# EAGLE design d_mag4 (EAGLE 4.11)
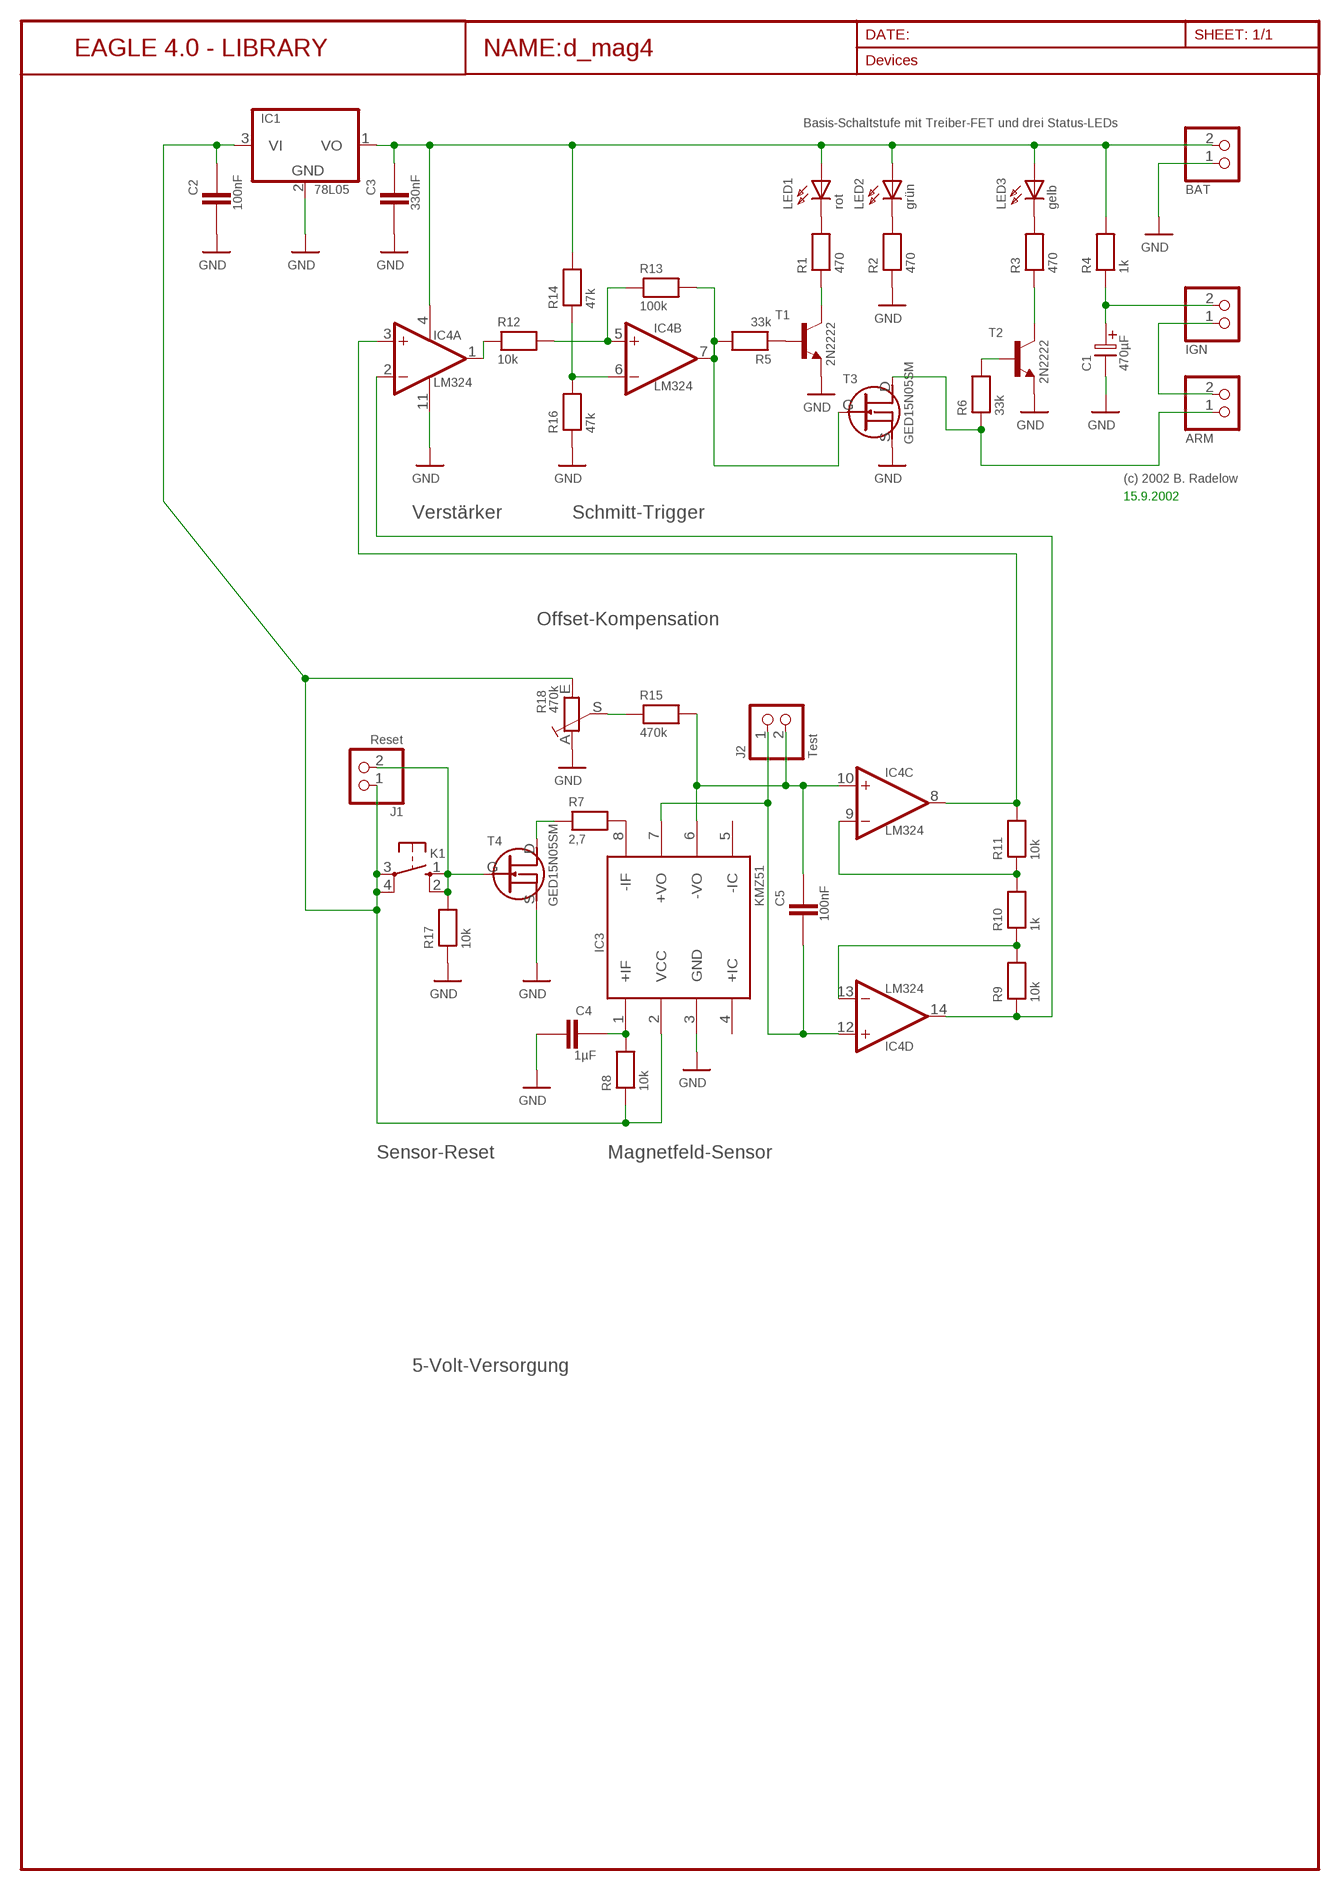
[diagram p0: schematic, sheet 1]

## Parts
ARM  PFOSTEN_1X2  [1X02]
BAT  PFOSTEN_1X2  [1X02]
C1  470µF  EC_470U  [E5-10,5]
C2  100nF  MKS2_10N-150N  [C5B2.5]
C3  330nF  MKS2_330N  [C5B3.5]
C4  1µF  MKS2_1000N  [C5B5]
C5  100nF  MKS2_10N-150N  [C5B2.5]
IC1  78L05  [TO92]
IC3  KMZ51  [SO8]
IC4  LM324  [DIL14]
IGN  PFOSTEN_1X2  [1X02]
J1  Reset  PFOSTEN_1X2  [1X02]
J2  Test  PFOSTEN_1X2  [1X02]
K1  TASTER_OMRON  [B3F-10XX]
LED1  rot  LED_3MM  [LED3MM]
LED2  grün  LED_3MM  [LED3MM]
LED3  gelb  LED_3MM  [LED3MM]
R1  470  R7,5  [0207/7]
R2  470  R7,5  [0207/7]
R3  470  R7,5  [0207/7]
R4  1k  R7,5  [0207/7]
R5  33k  R7,5  [0207/7]
R6  33k  R7,5  [0207/7]
R7  2,7  R7,5  [0207/7]
R8  10k  R7,5  [0207/7]
R9  10k  R7,5  [0207/7]
R10  1k  R7,5  [0207/7]
R11  10k  R7,5  [0207/7]
R12  10k  R7,5  [0207/7]
R13  100k  R7,5  [0207/7]
R14  47k  R7,5  [0207/7]
R15  470k  R7,5  [0207/7]
R16  47k  R7,5  [0207/7]
R17  10k  R7,5  [0207/7]
R18  470k  TRIM-S64Y  [S64Y]
T1  2N2222  [TO18]
T2  2N2222  [TO18]
T3  GED15N05SM  [TO252]
T4  GED15N05SM  [TO252]

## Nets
5VOLT: C2.1 IC1.3(VI) IC3.2(VCC) J1.1 K1.3(P) K1.4(P1) R8.1 R18.E(1E)
GND: BAT.1 C1.- C2.2 C3.2 C4.2 IC1.2(GND) IC3.3(GND) IC4.11(A:GND) R2.1 R16.1 R17.1 R18.A(1A) T1.1(E) T2.1(E) T3.S T4.S
N$1: ARM.2 IGN.1
N$2: LED2.K(C) R2.2
N$3: LED1.K(C) R1.2
N$4: LED3.K(C) R3.2
N$6: IC4.7(B:OUT) R5.2 R13.2 T3.G
N$8: ARM.1 R6.1 T3.D
N$11: C1.+ IGN.2 R4.1
N$12: R5.1 T1.2(B)
N$16: IC4.5(B:+IN) R12.2 R13.1
N$17: R1.1 T1.3(C)
N$18: IC4.6(B:-IN) R14.1 R16.2
N$19: IC4.9(C:-IN) R10.2 R11.1
N$20: IC4.13(D:-IN) R9.2 R10.1
N$21: IC4.2(A:-IN) IC4.14(D:OUT) R9.1
N$22: IC4.3(A:+IN) IC4.8(C:OUT) R11.2
N$23: C4.1 IC3.1(+IF) R8.2
N$24: C5.2 IC3.7(+VO) IC4.12(D:+IN) J2.1
N$25: R3.1 T2.3(C)
N$26: J1.2 K1.1(S) K1.2(S1) R17.2 T4.G
N$27: R6.2 T2.2(B)
N$28: C5.1 IC3.6(-VO) IC4.10(C:+IN) J2.2 R15.2
N$29: R15.1 R18.S(1S)
N$30: IC3.8(-IF) R7.2
N$31: IC4.1(A:OUT) R12.1
N$37: R7.1 T4.D
V+: BAT.2 C3.1 IC1.1(VO) IC4.4(A:V+) LED1.A LED2.A LED3.A R4.2 R14.2
Unconnected: IC3.4(+IC) IC3.5(-IC)

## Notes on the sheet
- Basis-Schaltstufe mit Treiber-FET und drei Status-LEDs
- (c) 2002 B. Radelow
- 15.9.2002
- Verstärker | Schmitt-Trigger
- Offset-Kompensation
- Sensor-Reset | Magnetfeld-Sensor
- 5-Volt-Versorgung

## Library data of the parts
ARM BAT IGN J1 J2 = _d_serie:PFOSTEN_1X2: Pfosten 2x1
C1 = _d_serie:EC_470U: 470µF 16V, Höhe 17mm
C2 C5 = _d_serie:MKS2_10N-150N: WIMA MKS2 Folienkondensator
C3 = _d_serie:MKS2_330N: WIMA MKS2 Folienkondensator 330nF
C4 = _d_serie:MKS2_1000N: WIMA MKS2 Folienkondensator 1µF
IC1 = _d_serie:78L05: Voltage Regulator 5V
IC3 = _d_serie:KMZ51: Magnetic Field Sensor
IC4 = _d_serie:LM324: LM324 - quad OpAmp
K1 = _d_serie:TASTER_OMRON: Taster, Omron
LED1-LED3 = _d_serie:LED_3MM
R1-R17 = _d_serie:R7,5: Widerstand 0,3 Watt liegend
R18 = _d_serie:TRIM-S64Y: Trimmer S64Y
T1 T2 = _d_serie:2N2222
T3 T4 = _d_serie:GED15N05SM: N-Channel Power-FET

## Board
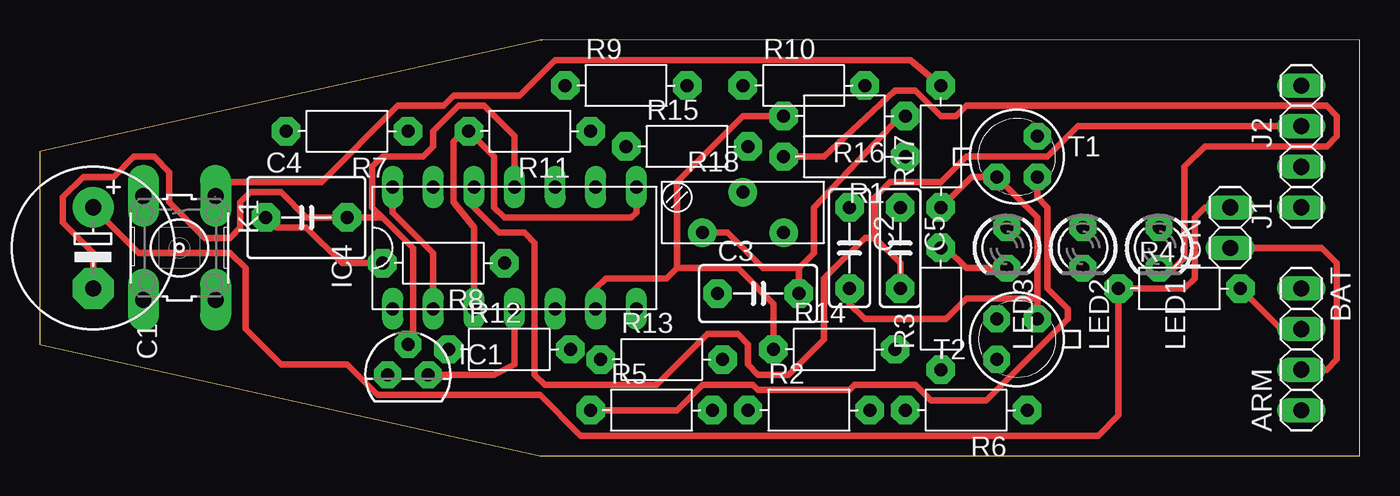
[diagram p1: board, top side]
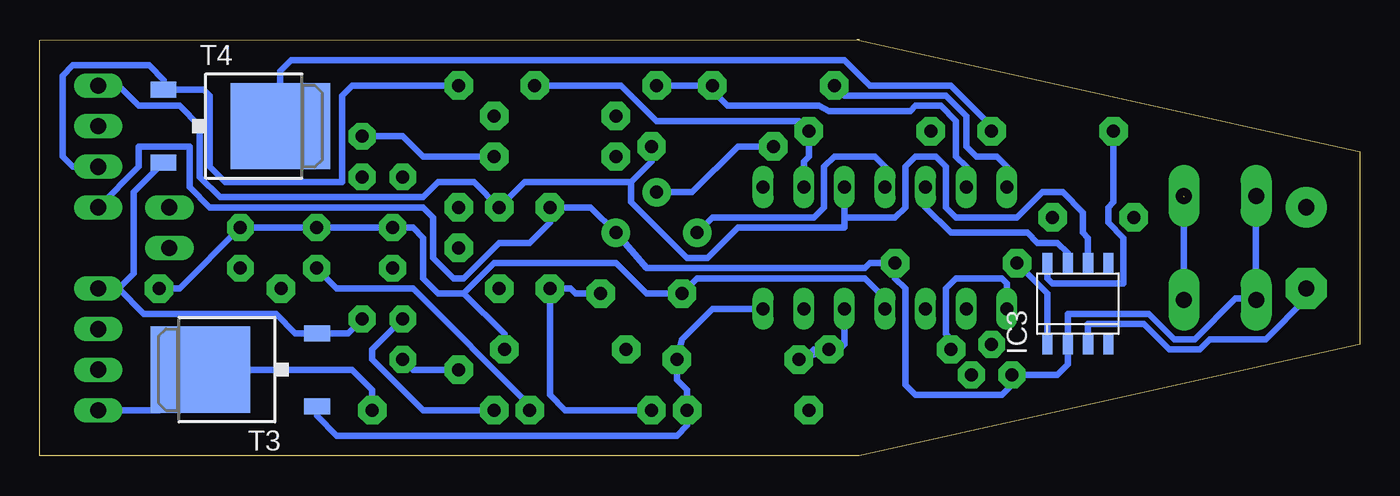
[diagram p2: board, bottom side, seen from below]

Size 82.54 x 26.04 mm. Coordinates in mm from the lower left corner, seen from the top.
Outline: 31.44,26.04 82.54,26.03 82.54,0 31.27,0 0,6.99 0,19.04 31.44,26.04
Outline: 31.27,26.04 31.44,26.04
Copper layers (1*16): Top 0.035mm / dielectric 1.5mm / Bottom 0.035mm
Design rules "default": minimum track width 10mil, minimum drill 24mil, track to track 8mil, track to pad 8mil, pad to pad 8mil, via to via 8mil, smd to smd 8mil, copper to edge 40mil, drill to drill 8mil, minimum pad ring 10mil, minimum via ring 8mil, stop-mask expansion 4mil, vias tented up to drill 0mil, thermal gap 10mil

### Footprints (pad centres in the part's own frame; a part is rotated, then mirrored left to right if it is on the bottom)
1X02 = drill 1.016 long: 1 -1.27,0; 2 1.27,0
E5-10,5 = drill 1.016 pad 2.54 round: + -2.54,0 | drill 1.016 pad 2.54 octagon: - 2.54,0
C5B2.5 = drill 0.813 pad 1.778 octagon: 1 -2.54,0; 2 2.54,0
C5B3.5 = drill 0.813 pad 1.778 octagon: 1 -2.54,0; 2 2.54,0
C5B5 = drill 0.813 pad 1.778 octagon: 1 -2.54,0; 2 2.54,0
TO92 = drill 0.813 pad 1.676 octagon: 1 1.27,0; 2 0,1.905; 3 -1.27,0
SO8 = smd 0.635 x 1.27: 1 -1.905,-2.54; 2 -0.635,-2.54; 3 0.635,-2.54; 4 1.905,-2.54; 5 1.905,2.54; 6 0.635,2.54; 7 -0.635,2.54; 8 -1.905,2.54
DIL14 = drill 0.813 long: 1 -7.62,-3.81; 2 -5.08,-3.81; 3 -2.54,-3.81; 4 0,-3.81; 5 2.54,-3.81; 6 5.08,-3.81; 7 7.62,-3.81; 8 7.62,3.81; 9 5.08,3.81; 10 2.54,3.81; 11 0,3.81; 12 -2.54,3.81; 13 -5.08,3.81; 14 -7.62,3.81
B3F-10XX = drill 1.016 pad 1.93 long: 1 -3.251,2.261; 2 3.251,2.261; 3 -3.251,-2.261; 4 3.251,-2.261
LED3MM = drill 0.813 pad 1.676 octagon: A -1.27,0; K 1.27,0
0207/7 = drill 0.813 pad 1.778 octagon: 1 -3.81,0; 2 3.81,0
S64Y = drill 0.813 pad 1.778 round: A -2.54,-1.27; E 2.54,-1.27; S 0,1.27
TO18 = drill 0.813 pad 1.676 octagon: 1 -1.27,-1.27; 2 1.27,-1.27; 3 1.27,1.27
TO252 = smd 5.4 x 6.2: D 0,1.23 | smd 1 x 1.6: G -2.28,-6.07; S 2.28,-6.07

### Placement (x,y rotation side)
ARM  78.89,4.13 90 top
BAT  78.89,9.21 270 top
C1  3.33,13.02 270 top
C2  50.64,13.02 270 top
C3  44.92,10.16 0 top
C4  16.66,14.92 0 top
C5  53.81,13.02 270 top
IC1  23.01,5.08 0 top
IC3  17.61,9.53 0 bottom
IC4  29.68,13.02 0 top
IGN  74.45,14.29 90 top
J1  78.89,16.83 90 top
J2  78.89,21.91 90 top
K1  8.72,13.02 270 top
LED1  70,13.02 270 top
LED2  65.24,13.02 270 top
LED3  60.48,13.02 270 top
R1  50.32,18.73 180 top
R2  48.09,2.86 0 top
R3  56.35,9.21 90 top
R4  71.27,10.48 0 top
R5  38.25,2.86 0 top
R6  57.94,2.86 180 top
R7  19.2,20.32 180 top
R8  25.23,12.06 180 top
R9  36.66,23.18 0 top
R10  47.78,23.18 0 top
R11  30.63,20.32 180 top
R12  29.36,6.67 0 top
R13  38.89,6.03 0 top
R14  49.68,6.67 0 top
R15  40.47,19.37 0 top
R16  50.32,21.27 180 top
R17  56.35,19.37 90 top
R18  43.97,15.24 0 top
T1  61.11,18.73 0 top
T2  61.11,7.3 180 top
T3  71.27,5.4 90 bottom
T4  68.73,20.64 270 bottom

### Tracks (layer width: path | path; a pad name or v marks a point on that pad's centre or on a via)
5VOLT
  Top 0.406: IC1.3 21.11,4.76
  Bottom 0.406: J1.1 76.35,18.1 76.35,19.37 73.18,19.37 73.18,16.83 71.91,15.56 58.57,15.56 57.94,14.92 57.94,12.38 56.67,11.11 56.03,11.11 53.81,13.34 51.9,13.34 50.64,14.61 C2.1 48.09,15.56 R18.E 44.6,11.75 30.95,11.75 30.63,12.06 R8.1 29.04,11.11 28.41,10.48 28.41,4.44 27.78,3.81 22.38,3.81 21.74,4.44 IC1.3 | 6.46,10.83 6.5,10.79 | 6.46,10.83 6.46,11.07 6.5,10.79 | K1.4 6.46,10.83 | K1.3 6.5,17.5 6.5,10.79 | 18.25,5.72 IC3.2 | 21.43,5.08 21.43,5.4 IC1.3 | 21.43,5.08 IC1.3 | 21.43,5.08 19.52,5.08 18.89,5.08 18.25,5.72 | 18.25,5.72 18.25,8.89 13.17,8.89 11.58,7.3 10.31,7.3 7.77,9.84 6.5,9.84 6.5,10.79
GND
  Top 0.406: 47.46,11.75 45.24,11.75 43.01,13.97 R18.A | 21.43,14.92 20.79,15.56 20.79,18.1 21.43,18.73 23.97,18.73 24.6,19.37 24.6,20.32 26.19,21.91 27.78,21.91 29.68,20 IC4.11 | R17.1 58.25,17.46 T1.1 62.38,14.92 62.38,9.84 | 62.38,9.84 T2.1 | C2.2 50.64,9.53 51.59,8.57 56.67,8.57 57.94,9.84 62.38,9.84 | R16.1 53.81,21.27 48.41,15.56 48.41,12.7 47.46,11.75 | 47.46,11.75 C3.2 | IC1.2 23.33,7.3 23.33,13.02 21.43,14.92 | 21.43,14.92 C4.2 16.66,14.92 15.08,16.51 13.17,16.51 12.54,15.87 12.54,14.29 11.9,13.65 10.31,13.65 8.09,15.87 8.09,17.78 7.14,18.73 5.87,18.73 4.6,17.46 2.69,17.46 1.42,16.19 1.42,14.61 3.33,12.7 C1.-
  Bottom 0.406: T2.1 63.28,7.68 T3.S 66.57,7.68 67.78,8.89 76.03,8.89 77.62,10.48 | 77.62,10.48 BAT.1 | 77.62,10.48 76.67,11.43 76.67,16.51 74.82,18.36 T4.S | R2.1 49.68,2.86 50.64,3.81 C2.2 49.37,10.48 49.05,10.16 C3.2 | R18.A 40.47,14.92 34.12,14.92 33.49,15.56 33.49,18.1 32.86,18.73 30.32,18.73 29.68,18.1 IC4.11 | C1.- 3.33,9.84 5.87,7.3 9.36,7.3 9.99,6.67 11.9,6.67 13.49,8.26 16.98,8.26 IC3.3
N$1
  Top 0.406: ARM.2 80.48,5.4 81.12,6.03 81.12,12.06 80.16,13.02 IGN.1
N$2
  Bottom 0.406: R2.2 51.9,3.17 59.21,10.48 63.97,10.48 LED2.K
N$3
  Top 0.406: LED1.K 70.95,11.75 71.59,12.38 71.59,18.1 72.86,19.37 80.48,19.37 81.12,20 81.12,21.27 80.48,21.91 57.94,21.91 57.3,21.27 56.35,21.27 54.76,22.86 53.49,22.86 49.05,18.73 R1.2
N$4
  Top 0.406: R3.2 56.67,13.02 57.94,11.75 LED3.K
N$6
  Bottom 0.406: T3.G 65.2,2.5 63.97,1.27 42.7,1.27 42.06,1.91 R5.2 42.06,4.13 42.7,4.76 R13.2 42.38,7.3 40.47,9.21 IC4.7
N$8
  Bottom 0.406: ARM.1 75.08,2.86 72.54,5.4 | R6.1 61.75,4.13 63.02,5.4 72.54,5.4 | 72.54,5.4 T3.D
N$11
  Top 0.406: C1.+ 6.18,12.7 11.9,12.7 12.85,11.75 12.85,7.94 15.08,5.72 19.2,5.72 21.11,3.81 31.27,3.81 33.81,1.27 66.19,1.27 67.46,2.54 67.46,9.84 68.1,10.48 R4.1 71.59,10.48 72.23,11.11 72.23,14.92 72.86,15.56 IGN.2
N$12
  Top 0.406: R5.1 39.84,2.86 41.43,4.44 44.6,4.44 44.92,4.13 50.64,4.13 50.95,4.44 54.76,4.44 55.72,3.49 59.21,3.49 64.29,8.57 64.29,9.21 63.02,10.48 63.02,15.56 62.38,16.19 T1.2
N$16
  Bottom 0.406: R12.2 R13.1 34.76,6.03 34.12,6.67 R12.2 | R12.2 32.54,6.67 32.22,6.98 IC4.5
N$17
  Bottom 0.406: T1.3 59.84,20 58.57,18.73 R1.1
N$18
  Top 0.406: R14.1 45.87,9.53 43.65,11.75 39.84,11.75 | IC4.6 34.76,10.48 35.4,11.11 39.21,11.11 39.84,11.75 | R16.2 43.97,21.27 39.84,17.14 39.84,11.75
N$19
  Bottom 0.406: IC4.9 34.76,18.42 34.44,18.73 R11.1 35.08,20.95 43.97,20.95 46.19,23.18 R10.2
N$20
  Bottom 0.406: R10.1 R9.2 40.79,23.18 39.52,21.91 33.81,21.91 33.17,21.59 28.09,21.59 27.78,21.91 26.19,21.91 25.23,20.95 25.23,18.73 24.6,18.1 IC4.13
N$21
  Top 0.406: IC4.14 22.06,15.24 24.6,12.7 IC4.2
  Bottom 0.406: IC4.14 22.06,18.1 22.69,18.73 23.97,18.73 24.6,19.37 24.6,21.27 25.87,22.54 32.22,22.54 R9.1
N$22
  Top 0.406: IC4.3 27.14,14.29 25.87,15.87 25.87,19.69 26.51,20.32 R11.2 28.41,18.73 28.41,15.56 29.04,14.92 36.98,14.92 37.3,15.24 IC4.8
N$23
  Top 0.406: C4.1 14.76,14.29 16.66,14.29 18.89,12.06 R8.2
  Bottom 0.406: IC3.1 19.52,10.16 R8.2
N$24
  Top 0.406: 52.22,13.65 51.59,13.65 49.05,11.11 49.05,7.3 46.83,5.08 44.92,5.08 44.29,5.72 44.29,6.98 43.65,7.62 41.75,7.62 38.57,4.44 31.58,4.44 30.95,5.08 30.95,13.34 30.32,13.97 28.73,13.97 27.14,15.56 IC4.12 | J2.1 64.92,20.64 63.02,18.73 57.94,18.73 56.35,17.14 53.17,17.14 52.22,16.19 52.22,13.65 | 52.22,13.65 53.81,12.06 C5.2
  Bottom 0.406: IC3.7 18.25,12.7 18.89,13.34 20.15,13.34 20.79,13.97 25.55,13.97 27.14,15.56 IC4.12
N$25
  Bottom 0.406: T2.3 59.21,5.4 R3.1
N$26  (1 unrouted)
  Top 0.406: R17.2 54.45,24.76 32.22,24.76 30,22.54 25.87,22.54 25.23,21.91 22.38,21.91 17.61,17.14 11.9,17.14 10.95,16.19
  Bottom 0.406: K1.1 11.02,16.27 10.95,17.14 10.99,17.11 K1.1 | K1.2 K1.1 | J1.2 80.48,18.1 81.12,18.73 81.12,23.81 80.48,24.45 75.72,24.45 74.8,23.53 T4.G 72.28,22.92 71.91,22.54 71.91,18.1 70.95,17.14 63.65,17.14 63.65,22.54 63.02,23.18 R17.2
N$27
  Bottom 0.406: R6.2 58.57,2.86 61.75,6.03 61.75,6.67 T2.2
N$28
  Bottom 0.406: 32.22,14.92 32.22,14.29 38.89,14.29 40.79,12.38 42.06,12.38 45.55,15.87 45.55,17.14 | 32.22,14.92 IC4.10 | 45.55,17.14 44.29,18.42 R15.2 | 45.55,17.14 52.22,17.14 C5.1 55.4,17.14 57.62,17.14 58.57,16.19 71.27,16.19 72.54,17.46 72.54,20.64 73.81,21.91 76.35,21.91 77.62,23.18 J2.2 | IC3.6 16.98,13.65 17.3,13.97 17.3,15.24 18.57,16.51 19.84,16.51 21.43,14.92 25.23,14.92 25.87,15.56 25.87,18.1 26.51,18.73 27.78,18.73 28.41,18.1 28.41,15.56 29.04,14.92 32.22,14.92
N$29
  Bottom 0.406: R18.S 41.75,16.51 38.89,19.37 R15.1
N$30
  Bottom 0.406: IC3.8 19.52,11.11 19.2,10.79 14.76,10.79 14.76,13.65 15.71,14.61 15.71,15.56 15.39,15.87 R7.2
N$31
  Bottom 0.406: R12.1 25.55,7.3 25.87,7.62 25.87,10.48 25.23,11.11 22.38,11.11 22.06,10.79 IC4.1
N$37
  Bottom 0.406: T4.D 67.5,24.09 66.83,24.76 32.22,24.76 30.63,23.18 25.55,23.18 23.01,20.64 R7.1
V+
  Top 0.406: BAT.2 77.62,7.94 R4.2 | IC1.1 28.41,5.08 29.68,5.72 IC4.4
  Bottom 0.406: 56.03,10.16 57.62,10.16 58.57,11.11 58.57,13.65 59.21,14.29 LED3.A LED2.A LED1.A 73.81,10.48 R4.2 | R14.2 53.49,7.62 56.03,10.16 | 56.03,10.16 54.13,12.06 46.51,12.06 44.6,10.16 C3.1 41.43,11.11 30.95,11.11 29.68,9.84 IC4.4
